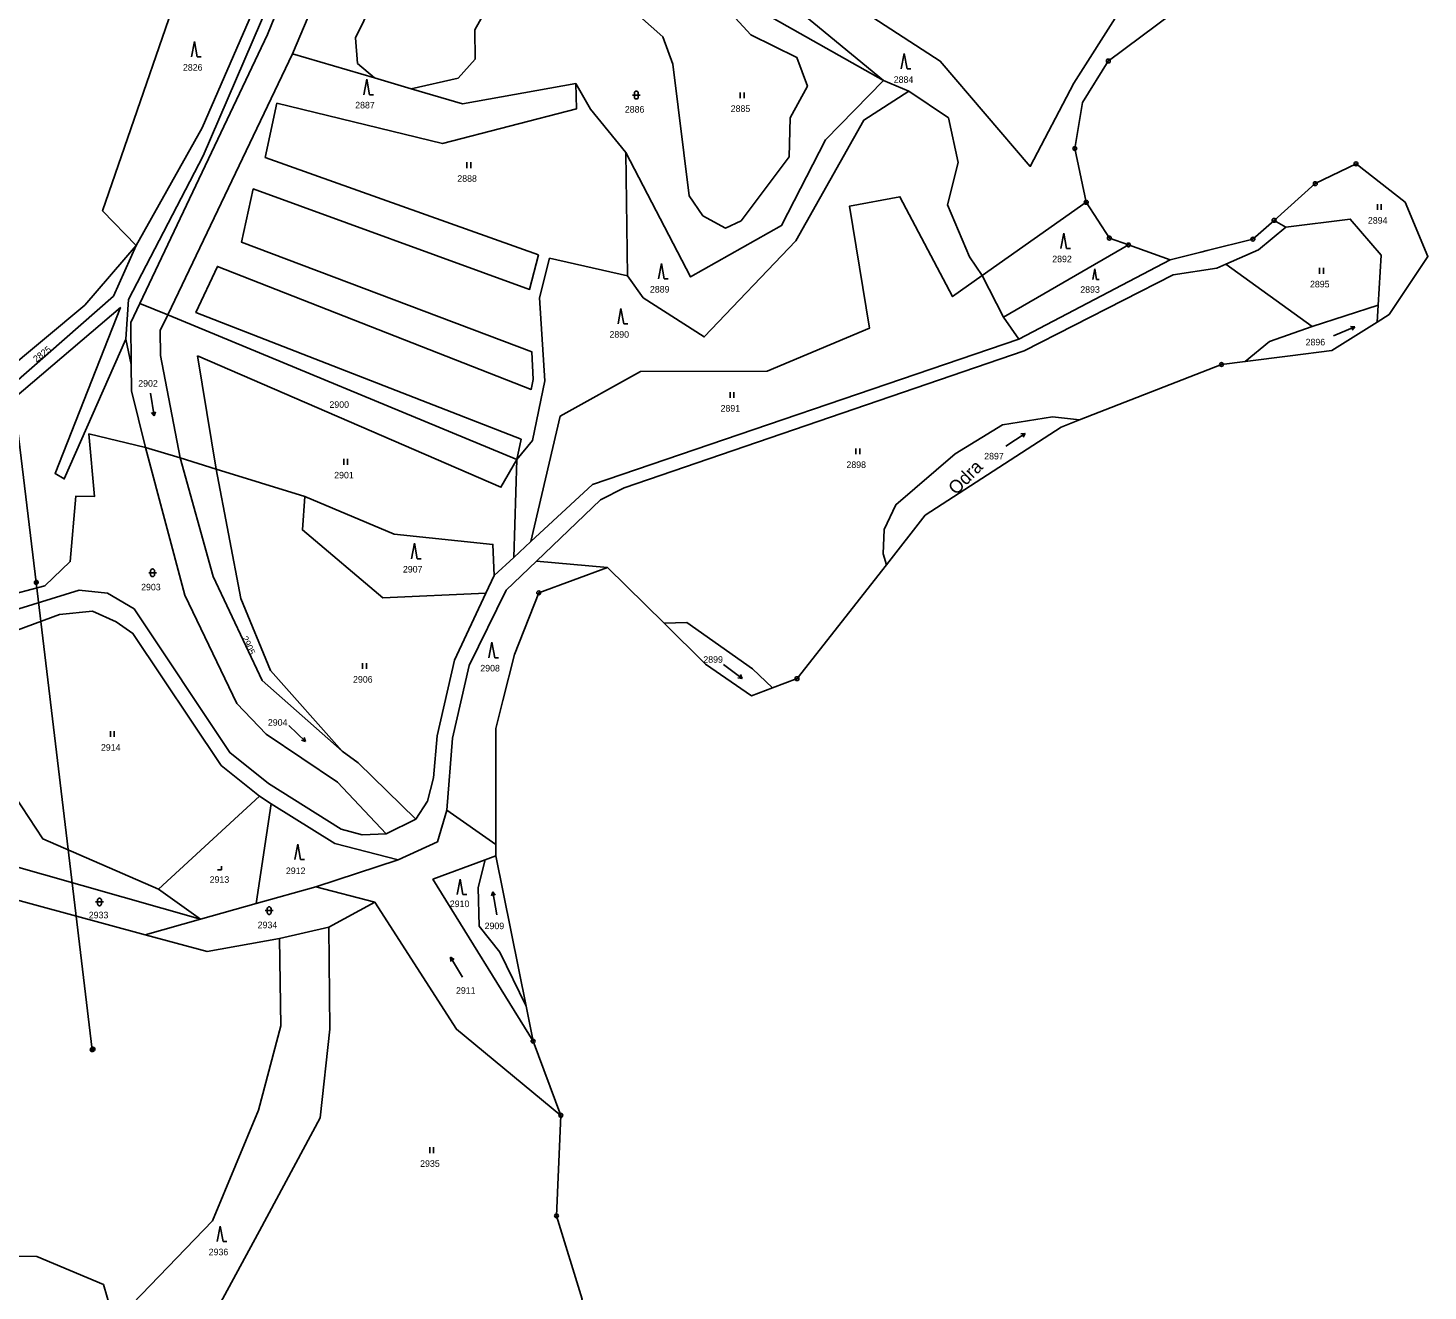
# Model space of a CAD drawing. Extents: x -504988 to -494607, y -1123820 to -1114018.
# Drawn here: x -496650.7 to -496288.6, y -1121578.3 to -1121251.8 of the extents above; entities that cross this region are included whole.
import ezdxf

# ---------------------------------------------------------------- set-up
doc = ezdxf.new("R2010")
doc.units = 0
for name, color, linetype in [('Hranice parcel', 7, 'Continuous'), ('Parcelní čísla', 7, 'Continuous'), ('Pop  PČ popisy', 7, 'Continuous'), ('Poz předměty', 7, 'Continuous'), ('Značky bodu BP', 7, 'Continuous'), ('Značky kultur', 7, 'Continuous')]:
    doc.layers.add(name, color=color, linetype=linetype)

msp = doc.modelspace()

# ---------------------------------------------------------------- linework, layer by layer
at = {"layer": 'Hranice parcel'}
for p, q in [((-496470.68, -1121231.3), (-496429.48, -1121265.34)), ((-496429.48, -1121265.34), (-496476.36, -1121238.83)), ((-496582.31, -1121258.44), (-496614.58, -1121325.9)), ((-496561.1, -1121264.68), (-496582.31, -1121258.44)), ((-496551.6, -1121267.48), (-496561.1, -1121264.68)), ((-496429.48, -1121265.34), (-496422.9, -1121268.07)), ((-496422.9, -1121268.07), (-496412.65, -1121274.96)), ((-496495.64, -1121315.83), (-496496.12, -1121283.91)), ((-496403.9, -1121315.79), (-496377.01, -1121296.83)), ((-496325.37, -1121303.26), (-496332.46, -1121309.1)), ((-496328.42, -1121301.49), (-496325.37, -1121303.26)), ((-496398.42, -1121326.56), (-496366.07, -1121307.85)), ((-496355.33, -1121311.69), (-496366.07, -1121307.85)), ((-496332.46, -1121309.1), (-496340.89, -1121312.79)), ((-496515.81, -1121311.23), (-496495.64, -1121315.83)), ((-496394.48, -1121332.18), (-496355.33, -1121311.69)), ((-496340.89, -1121312.79), (-496318.62, -1121328.96)), ((-496398.42, -1121326.56), (-496403.9, -1121315.79)), ((-496621.74, -1121322.97), (-496614.58, -1121325.9)), ((-496318.62, -1121328.96), (-496301.51, -1121323.39)), ((-496301.51, -1121323.39), (-496301.79, -1121327.79)), ((-496524.26, -1121363.37), (-496614.58, -1121325.9)), ((-496394.48, -1121332.18), (-496398.42, -1121326.56)), ((-496301.79, -1121327.79), (-496298.64, -1121325.8)), ((-496624.02, -1121338.8), (-496625.44, -1121332.21)), ((-496504.73, -1121369.78), (-496394.48, -1121332.18)), ((-496602.07, -1121365.82), (-496606.86, -1121336.5)), ((-496383.53, -1121354.95), (-496378.78, -1121353.1)), ((-496620.34, -1121360.24), (-496611.32, -1121362.94)), ((-496524.26, -1121363.37), (-496523.18, -1121358.1)), ((-496524.26, -1121363.37), (-496520.22, -1121358.42)), ((-496611.32, -1121362.94), (-496602.07, -1121365.82)), ((-496525.08, -1121388.67), (-496524.26, -1121363.37)), ((-496602.07, -1121365.82), (-496579.07, -1121372.92)), ((-496595.65, -1121399.25), (-496602.07, -1121365.82)), ((-496520.67, -1121384.57), (-496504.73, -1121369.78)), ((-496525.08, -1121388.67), (-496520.67, -1121384.57)), ((-496530.13, -1121393.36), (-496525.08, -1121388.67)), ((-496519.17, -1121389.66), (-496500.84, -1121391.27)), ((-496530.13, -1121393.36), (-496532.29, -1121397.87)), ((-496500.84, -1121391.27), (-496486.21, -1121405.66)), ((-496569.41, -1121438.72), (-496590.16, -1121420.45)), ((-496565.28, -1121441.81), (-496569.41, -1121438.72)), ((-496550.42, -1121456.31), (-496565.28, -1121441.81)), ((-496616.96, -1121474.47), (-496590.86, -1121450.37)), ((-496590.86, -1121450.37), (-496587.81, -1121452.35)), ((-496587.81, -1121452.35), (-496591.67, -1121478.13)), ((-496542.35, -1121453.98), (-496529.73, -1121462.92)), ((-496550.42, -1121456.31), (-496558.08, -1121460.12)), ((-496529.73, -1121465.85), (-496532.47, -1121466.87)), ((-496529.73, -1121465.85), (-496529.73, -1121462.92)), ((-496521.89, -1121504.73), (-496529.73, -1121465.85)), ((-496554.97, -1121466.82), (-496576.27, -1121473.8)), ((-496620.4, -1121486.22), (-496662.4, -1121474.88)), ((-496606.05, -1121482.18), (-496616.96, -1121474.47)), ((-496591.67, -1121478.13), (-496576.27, -1121473.8)), ((-496576.27, -1121473.8), (-496560.96, -1121477.77)), ((-496591.67, -1121478.13), (-496606.05, -1121482.18)), ((-496572.91, -1121484.29), (-496560.96, -1121477.77)), ((-496620.4, -1121486.22), (-496606.05, -1121482.18)), ((-496585.65, -1121487.21), (-496572.91, -1121484.29)), ((-496604.4, -1121490.57), (-496620.4, -1121486.22)), ((-496585.65, -1121487.21), (-496604.4, -1121490.57)), ((-496520.07, -1121513.73), (-496521.89, -1121504.73)), ((-496512.9, -1121532.93), (-496520.07, -1121513.73)), ((-496590.79, -1121562.78), (-496604.12, -1121587.34))]:
    msp.add_line(p, q, dxfattribs=at)
for points in [[(-496528.08, -1121099.62), (-496543.62, -1121159.94), (-496554.91, -1121193.59), (-496582.31, -1121258.44)], [(-496625.44, -1121332.21), (-496624.69, -1121321.94), (-496605.39, -1121284.77), (-496573.58, -1121210.9), (-496558.7, -1121173.54), (-496551.05, -1121143.84), (-496538.11, -1121103.1)], [(-496538.11, -1121103.1), (-496539.96, -1121118.77), (-496556.52, -1121174.22), (-496588.8, -1121253.45), (-496621.74, -1121322.97)], [(-496475.72, -1121131.99), (-496375.19, -1121228.76), (-496368.33, -1121247.28), (-496380.21, -1121266), (-496391.51, -1121287.55), (-496414.78, -1121260.32), (-496466.99, -1121226.41)], [(-496561.1, -1121264.68), (-496565.51, -1121260.92), (-496565.99, -1121254.26), (-496538.21, -1121197.62), (-496535.05, -1121173.52), (-496531.79, -1121155.63), (-496528.33, -1121152.95), (-496525.09, -1121154.94)], [(-496606.21, -1121225.85), (-496631.4, -1121299.05), (-496622.71, -1121308.03)], [(-496514.87, -1121236.67), (-496517.64, -1121243.89), (-496532.34, -1121247.33), (-496535.12, -1121252.25), (-496535.06, -1121259.82), (-496539.41, -1121264.69), (-496551.6, -1121267.48)], [(-496588.6, -1121238.29), (-496605.69, -1121277.61), (-496622.71, -1121308.03)], [(-496477.36, -1121240.16), (-496474.75, -1121241.45), (-496463.73, -1121253.49), (-496451.83, -1121259.41), (-496449.13, -1121266.76), (-496453.58, -1121275.01), (-496453.87, -1121285.05), (-496466.27, -1121301.6), (-496470.32, -1121303.48), (-496476.18, -1121300.32), (-496479.7, -1121295.16), (-496483.91, -1121261.07), (-496486.53, -1121254.02), (-496499.38, -1121242.59)], [(-496377.01, -1121296.83), (-496379.97, -1121282.91), (-496377.95, -1121271.02), (-496371.3, -1121260.29), (-496350.41, -1121244.73)], [(-496518.7, -1121310.41), (-496589.33, -1121285.21), (-496586.34, -1121271.23), (-496543.49, -1121281.61), (-496508.86, -1121272.69), (-496509.04, -1121266.08)], [(-496551.6, -1121267.48), (-496538.34, -1121271.38), (-496509.04, -1121266.08)], [(-496509.04, -1121266.08), (-496505.23, -1121272.77), (-496496.12, -1121283.91)], [(-496496.12, -1121283.91), (-496479.32, -1121316.11), (-496455.8, -1121302.85), (-496444.46, -1121280.63), (-496429.48, -1121265.34)], [(-496495.64, -1121315.83), (-496491.58, -1121321.57), (-496475.8, -1121331.64), (-496452.12, -1121306.76), (-496434.53, -1121275.57), (-496422.9, -1121268.07)], [(-496412.65, -1121274.96), (-496410.16, -1121286.57), (-496412.87, -1121297.47)], [(-496307.24, -1121286.88), (-496317.77, -1121292), (-496328.42, -1121301.49)], [(-496298.64, -1121325.8), (-496288.62, -1121310.83), (-496294.56, -1121296.8), (-496307.24, -1121286.88)], [(-496523.18, -1121358.1), (-496607.26, -1121325.32), (-496601.73, -1121313.42), (-496520.55, -1121345.23), (-496520.02, -1121342.67), (-496520.39, -1121335.52), (-496595.47, -1121307.14), (-496592.46, -1121293.36), (-496520.96, -1121319.37), (-496518.7, -1121310.41)], [(-496520.67, -1121384.57), (-496513.05, -1121352.11), (-496492.32, -1121340.62), (-496459.56, -1121340.51), (-496433.09, -1121329.39), (-496438.26, -1121297.83), (-496425.2, -1121295.38), (-496411.56, -1121321.19), (-496403.9, -1121315.79)], [(-496412.87, -1121297.47), (-496407.24, -1121310.9), (-496403.9, -1121315.79)], [(-496366.07, -1121307.85), (-496371.03, -1121306.08), (-496377.01, -1121296.83)], [(-496328.42, -1121301.49), (-496333.9, -1121306.37), (-496345.7, -1121309.3), (-496347.4, -1121309.72), (-496355.33, -1121311.69)], [(-496325.37, -1121303.26), (-496308.71, -1121301.15), (-496300.69, -1121310.53), (-496301.51, -1121323.39)], [(-496622.71, -1121308.03), (-496636.01, -1121323.43), (-496668.45, -1121350.39), (-496671.83, -1121352.39)], [(-496622.71, -1121308.03), (-496628.61, -1121321.12), (-496667.38, -1121355.04)], [(-496520.22, -1121358.42), (-496517, -1121343.01), (-496518.43, -1121321.57), (-496515.81, -1121311.23)], [(-496519.17, -1121389.66), (-496502.65, -1121373.74), (-496496.53, -1121370.66), (-496393.03, -1121335.2), (-496354.54, -1121315.56), (-496343.25, -1121313.82), (-496340.89, -1121312.79)], [(-496667.38, -1121355.04), (-496664.77, -1121356.36), (-496626.79, -1121324.03), (-496643.72, -1121366.96), (-496641.34, -1121368.36), (-496625.44, -1121332.21)], [(-496621.74, -1121322.97), (-496624.1, -1121327.94), (-496624.02, -1121338.8)], [(-496614.58, -1121325.9), (-496616.52, -1121329.94), (-496616.41, -1121336.44), (-496611.32, -1121362.94)], [(-496335.88, -1121338), (-496324.29, -1121336.54), (-496313.45, -1121335.17), (-496301.79, -1121327.79)], [(-496318.62, -1121328.96), (-496329.64, -1121332.86), (-496335.88, -1121338)], [(-496624.02, -1121338.8), (-496623.97, -1121345.57), (-496620.34, -1121360.24)], [(-496606.86, -1121336.5), (-496528.4, -1121370.53), (-496524.26, -1121363.37)], [(-496378.78, -1121353.1), (-496342.03, -1121338.78), (-496335.88, -1121338)], [(-496378.78, -1121353.1), (-496385.72, -1121352.32), (-496398.7, -1121354.35), (-496410.9, -1121361.85), (-496426.29, -1121375.04), (-496429.23, -1121381.46), (-496429.49, -1121387.76), (-496428.7, -1121390.55)], [(-496620.34, -1121360.24), (-496634.95, -1121356.72), (-496633.53, -1121372.93), (-496638.31, -1121372.79), (-496639.77, -1121389.71), (-496646.34, -1121396), (-496668.66, -1121401.9)], [(-496428.7, -1121390.55), (-496418.63, -1121377.71), (-496383.53, -1121354.95)], [(-496558.08, -1121460.12), (-496570.66, -1121446.78), (-496589.12, -1121434.38), (-496596.69, -1121426.45), (-496610.16, -1121398.44), (-496620.34, -1121360.24)], [(-496590.16, -1121420.45), (-496602.79, -1121393.6), (-496611.32, -1121362.94)], [(-496532.29, -1121397.87), (-496558.93, -1121399.13), (-496579.74, -1121381.55), (-496579.07, -1121372.92)], [(-496579.07, -1121372.92), (-496556.04, -1121382.68), (-496530.47, -1121385.29), (-496530.13, -1121393.36)], [(-496542.35, -1121453.98), (-496540.95, -1121435.35), (-496536.64, -1121416.56), (-496527.06, -1121397.15), (-496519.17, -1121389.66)], [(-496524.89, -1121413.73), (-496518.62, -1121397.8), (-496500.84, -1121391.27)], [(-496458.13, -1121422.4), (-496451.81, -1121420), (-496428.7, -1121390.55)], [(-496558.08, -1121460.12), (-496564.28, -1121460.43), (-496569.68, -1121458.96), (-496588.54, -1121447.1), (-496598.53, -1121439.12), (-496623.23, -1121401.96), (-496630.14, -1121397.89), (-496637.5, -1121397.15), (-496656.69, -1121403.1), (-496668.66, -1121401.9)], [(-496569.41, -1121438.72), (-496588.01, -1121417.93), (-496595.65, -1121399.25)], [(-496532.29, -1121397.87), (-496540.44, -1121415.25), (-496544.92, -1121434.75), (-496545.83, -1121445.67), (-496547.4, -1121451.7), (-496550.42, -1121456.31)], [(-496666.89, -1121406.29), (-496655.87, -1121408.36), (-496642.6, -1121403.41), (-496634.03, -1121402.52), (-496627.92, -1121405.3), (-496623.56, -1121408.29), (-496600.71, -1121442.49), (-496590.86, -1121450.37)], [(-496666.89, -1121406.29), (-496655.19, -1121437.57), (-496654.1, -1121450.38), (-496646.83, -1121461.45), (-496616.96, -1121474.47)], [(-496486.21, -1121405.66), (-496480.28, -1121405.44), (-496463.33, -1121417.49), (-496458.13, -1121422.4)], [(-496486.21, -1121405.66), (-496475.47, -1121416.23), (-496463.61, -1121424.48), (-496458.13, -1121422.4)], [(-496529.73, -1121462.92), (-496529.72, -1121442.66), (-496529.72, -1121432.92), (-496527.9, -1121425.68), (-496524.89, -1121413.73)], [(-496587.81, -1121452.35), (-496571.36, -1121462.63), (-496554.97, -1121466.82)], [(-496554.97, -1121466.82), (-496544.8, -1121462.19), (-496542.35, -1121453.98)], [(-496662.87, -1121463.73), (-496656.68, -1121467.79), (-496606.05, -1121482.18)], [(-496532.47, -1121466.87), (-496545.96, -1121471.86), (-496520.07, -1121513.73)], [(-496532.47, -1121466.87), (-496534.24, -1121474.02), (-496534.02, -1121483.97), (-496528.7, -1121490.71), (-496521.89, -1121504.73)], [(-496560.96, -1121477.77), (-496539.85, -1121510.68), (-496512.9, -1121532.93)], [(-496572.91, -1121484.29), (-496572.66, -1121510.67), (-496575.11, -1121533.56), (-496590.79, -1121562.78)], [(-496591.11, -1121531.58), (-496585.32, -1121509.8), (-496585.65, -1121487.21)], [(-496628.32, -1121586.51), (-496602.98, -1121560.16), (-496591.11, -1121531.58)], [(-496514.28, -1121602.59), (-496507.37, -1121580.43), (-496514.02, -1121558.9), (-496512.9, -1121532.93)], [(-496628.32, -1121586.51), (-496631.2, -1121576.69), (-496648.43, -1121569.4), (-496668.19, -1121569.15), (-496679.47, -1121580.69), (-496681.86, -1121588.4), (-496679.69, -1121596.75)]]:
    msp.add_lwpolyline(points, dxfattribs=at)
at = {"layer": 'Poz předměty'}
for p, q in [((-496662.04, -1121284.27), (-496648.56, -1121395.11)), ((-496648.56, -1121395.11), (-496634.09, -1121515.95))]:
    msp.add_line(p, q, dxfattribs=at)
for centre, radius in [((-496648.56, -1121395.11), 0.5), ((-496648.56, -1121395.11), 0.4), ((-496648.56, -1121395.11), 0.3), ((-496648.56, -1121395.11), 0.2), ((-496648.56, -1121395.11), 0.1), ((-496634.09, -1121515.95), 0.5), ((-496634.09, -1121515.95), 0.4), ((-496633.89, -1121515.82), 0.5), ((-496634.09, -1121515.95), 0.3), ((-496633.89, -1121515.82), 0.4), ((-496634.09, -1121515.95), 0.2), ((-496633.89, -1121515.82), 0.3), ((-496634.09, -1121515.95), 0.1), ((-496633.89, -1121515.82), 0.2), ((-496633.89, -1121515.82), 0.1)]:
    msp.add_circle(centre, radius, dxfattribs=at)
at = {"layer": 'Značky bodu BP'}
for centre, radius in [((-496371.3, -1121260.29), 0.5), ((-496371.3, -1121260.29), 0.0303), ((-496379.97, -1121282.91), 0.5), ((-496379.97, -1121282.91), 0.0303), ((-496307.24, -1121286.88), 0.5), ((-496307.24, -1121286.88), 0.0303), ((-496317.77, -1121292), 0.5), ((-496317.77, -1121292), 0.0303), ((-496377.01, -1121296.83), 0.5), ((-496377.01, -1121296.83), 0.0303), ((-496328.42, -1121301.49), 0.5), ((-496328.42, -1121301.49), 0.0303), ((-496371.03, -1121306.08), 0.5), ((-496371.03, -1121306.08), 0.0303), ((-496333.9, -1121306.37), 0.5), ((-496333.9, -1121306.37), 0.0303), ((-496366.07, -1121307.85), 0.5), ((-496366.07, -1121307.85), 0.0303), ((-496342.03, -1121338.78), 0.5), ((-496342.03, -1121338.78), 0.0303), ((-496518.62, -1121397.8), 0.5), ((-496518.62, -1121397.8), 0.0303), ((-496451.81, -1121420), 0.5), ((-496451.81, -1121420), 0.0303), ((-496520.07, -1121513.73), 0.5), ((-496520.07, -1121513.73), 0.0303), ((-496512.9, -1121532.93), 0.5), ((-496512.9, -1121532.93), 0.0303), ((-496514.02, -1121558.9), 0.5), ((-496514.02, -1121558.9), 0.0303)]:
    msp.add_circle(centre, radius, dxfattribs=at)
at = {"layer": 'Značky kultur'}
for p, q in [((-496607.66, -1121255.24), (-496608.41, -1121259.24)), ((-496606.91, -1121259.24), (-496607.66, -1121255.24)), ((-496606.91, -1121259.24), (-496605.91, -1121259.24)), ((-496424.09, -1121258.33), (-496424.84, -1121262.33)), ((-496423.34, -1121262.33), (-496424.09, -1121258.33)), ((-496423.34, -1121262.33), (-496422.34, -1121262.33)), ((-496563.11, -1121265), (-496563.86, -1121269)), ((-496562.36, -1121269), (-496563.11, -1121265)), ((-496562.36, -1121269), (-496561.36, -1121269)), ((-496494.37, -1121269.09), (-496492.37, -1121269.09)), ((-496493.87, -1121268.59), (-496493.87, -1121269.59)), ((-496492.87, -1121269.59), (-496492.87, -1121268.59)), ((-496466.5, -1121269.91), (-496466.5, -1121268.41)), ((-496465.5, -1121269.91), (-496465.5, -1121268.41)), ((-496537.21, -1121287.98), (-496537.21, -1121286.48)), ((-496536.21, -1121287.98), (-496536.21, -1121286.48)), ((-496301.7, -1121298.81), (-496301.7, -1121297.31)), ((-496300.7, -1121298.81), (-496300.7, -1121297.31)), ((-496382.83, -1121304.77), (-496383.58, -1121308.77)), ((-496382.08, -1121308.77), (-496382.83, -1121304.77)), ((-496382.08, -1121308.77), (-496381.08, -1121308.77)), ((-496486.88, -1121312.62), (-496487.63, -1121316.62)), ((-496486.13, -1121316.62), (-496486.88, -1121312.62)), ((-496374.82, -1121314.07), (-496375.32, -1121316.75)), ((-496374.32, -1121316.75), (-496374.82, -1121314.07)), ((-496316.68, -1121315.28), (-496316.68, -1121313.78)), ((-496315.68, -1121315.28), (-496315.68, -1121313.78)), ((-496486.13, -1121316.62), (-496485.13, -1121316.62)), ((-496374.32, -1121316.75), (-496373.65, -1121316.75)), ((-496497.35, -1121324.29), (-496498.1, -1121328.29)), ((-496496.6, -1121328.29), (-496497.35, -1121324.29)), ((-496496.6, -1121328.29), (-496495.6, -1121328.29)), ((-496313.06, -1121331.35), (-496307.54, -1121329.01)), ((-496307.54, -1121329.01), (-496308.64, -1121328.93)), ((-496307.54, -1121329.01), (-496308.24, -1121329.85)), ((-496619.02, -1121346.15), (-496618.08, -1121352.07)), ((-496469.12, -1121347.39), (-496469.12, -1121345.89)), ((-496468.12, -1121347.39), (-496468.12, -1121345.89)), ((-496618.08, -1121352.07), (-496618.73, -1121351.19)), ((-496618.08, -1121352.07), (-496617.73, -1121351.03)), ((-496397.83, -1121359.85), (-496392.79, -1121356.58)), ((-496392.79, -1121356.58), (-496393.89, -1121356.7)), ((-496392.79, -1121356.58), (-496393.34, -1121357.54)), ((-496436.57, -1121361.98), (-496436.57, -1121360.48)), ((-496435.57, -1121361.98), (-496435.57, -1121360.48)), ((-496569.05, -1121364.68), (-496569.05, -1121363.18)), ((-496568.05, -1121364.68), (-496568.05, -1121363.18)), ((-496550.77, -1121385.01), (-496551.52, -1121389.01)), ((-496550.02, -1121389.01), (-496550.77, -1121385.01)), ((-496550.02, -1121389.01), (-496549.02, -1121389.01)), ((-496619.48, -1121392.63), (-496617.48, -1121392.63)), ((-496618.98, -1121392.13), (-496618.98, -1121393.13)), ((-496617.98, -1121393.13), (-496617.98, -1121392.13)), ((-496530.75, -1121410.59), (-496531.5, -1121414.59)), ((-496530, -1121414.59), (-496530.75, -1121410.59)), ((-496530, -1121414.59), (-496529, -1121414.59)), ((-496564.18, -1121417.49), (-496564.18, -1121415.99)), ((-496563.18, -1121417.49), (-496563.18, -1121415.99)), ((-496470.79, -1121416.34), (-496466, -1121419.95)), ((-496466, -1121419.95), (-496466.47, -1121418.96)), ((-496466, -1121419.95), (-496467.08, -1121419.77)), ((-496629.38, -1121435.09), (-496629.38, -1121433.59)), ((-496628.38, -1121435.09), (-496628.38, -1121433.59)), ((-496583.21, -1121432.1), (-496578.9, -1121436.27)), ((-496578.9, -1121436.27), (-496579.95, -1121435.95)), ((-496578.9, -1121436.27), (-496579.25, -1121435.23)), ((-496580.95, -1121462.8), (-496581.7, -1121466.8)), ((-496580.2, -1121466.8), (-496580.95, -1121462.8)), ((-496601.7, -1121469.48), (-496600.7, -1121469.48)), ((-496600.7, -1121469.48), (-496600.7, -1121468.48)), ((-496580.2, -1121466.8), (-496579.2, -1121466.8)), ((-496538.97, -1121471.84), (-496539.72, -1121475.84)), ((-496538.22, -1121475.84), (-496538.97, -1121471.84)), ((-496538.22, -1121475.84), (-496537.22, -1121475.84)), ((-496530.52, -1121475.15), (-496530.84, -1121476.2)), ((-496529.47, -1121481.06), (-496530.52, -1121475.15)), ((-496530.52, -1121475.15), (-496529.85, -1121476.02)), ((-496633.21, -1121477.75), (-496631.21, -1121477.75)), ((-496632.71, -1121477.25), (-496632.71, -1121478.25)), ((-496631.71, -1121478.25), (-496631.71, -1121477.25)), ((-496589.33, -1121479.99), (-496587.33, -1121479.99)), ((-496588.83, -1121479.49), (-496588.83, -1121480.49)), ((-496587.83, -1121480.49), (-496587.83, -1121479.49)), ((-496538.36, -1121497.19), (-496541.45, -1121492.05)), ((-496541.45, -1121492.05), (-496541.37, -1121493.15)), ((-496541.45, -1121492.05), (-496540.51, -1121492.63)), ((-496546.82, -1121542.69), (-496546.82, -1121541.19)), ((-496545.82, -1121542.69), (-496545.82, -1121541.19)), ((-496601, -1121561.56), (-496601.75, -1121565.56)), ((-496600.25, -1121565.56), (-496601, -1121561.56)), ((-496600.25, -1121565.56), (-496599.25, -1121565.56))]:
    msp.add_line(p, q, dxfattribs=at)
for centre, start, end in [((-496493.37, -1121268.59), 0, 180), ((-496493.37, -1121269.59), 180, 359.9879), ((-496618.48, -1121392.13), 0, 180), ((-496618.48, -1121393.13), 180, 359.9879), ((-496632.21, -1121477.25), 0, 180), ((-496632.21, -1121478.25), 180, 359.9879), ((-496588.33, -1121479.49), 0, 180), ((-496588.33, -1121480.49), 180, 359.9879)]:
    msp.add_arc(centre, 0.5, start, end, dxfattribs=at)

# ---------------------------------------------------------------- texts
at = {"layer": 'Parcelní čísla'}
for s, p in [('2826', (-496610.63, -1121262.79)), ('2884', (-496426.8, -1121265.95)), ('2887', (-496566.08, -1121272.55)), ('2886', (-496496.34, -1121273.64)), ('2885', (-496468.96, -1121273.46)), ('2888', (-496539.67, -1121291.53)), ('2894', (-496304.16, -1121302.36)), ('2892', (-496385.8, -1121312.32)), ('2895', (-496319.14, -1121318.83)), ('2889', (-496489.85, -1121320.17)), ('2893', (-496378.55, -1121320.23)), ('2890', (-496500.32, -1121331.84)), ('2896', (-496320.27, -1121333.83)), ('2902', (-496622.19, -1121344.5)), ('2900', (-496572.74, -1121349.98)), ('2891', (-496471.58, -1121350.94)), ('2898', (-496439.03, -1121365.53)), ('2897', (-496403.4, -1121363.32)), ('2901', (-496571.51, -1121368.23)), ('2907', (-496553.74, -1121392.56)), ('2903', (-496621.45, -1121397.18)), ('2899', (-496476.04, -1121415.9)), ('2908', (-496533.72, -1121418.14)), ('2906', (-496566.64, -1121421.04)), ('2904', (-496588.66, -1121432.18)), ('2914', (-496631.84, -1121438.64)), ('2912', (-496584, -1121470.54)), ('2913', (-496603.71, -1121472.79)), ('2933', (-496634.98, -1121481.98)), ('2910', (-496541.61, -1121479.08)), ('2934', (-496591.3, -1121484.54)), ('2909', (-496532.61, -1121484.78)), ('2911', (-496540.01, -1121501.48)), ('2935', (-496549.28, -1121546.24)), ('2936', (-496603.97, -1121569.11))]:
    msp.add_text(s, height=1.7, dxfattribs=at).set_placement(p)
for s, rotation, p in [('2825', 38, (-496648.54, -1121338.28)), ('2905', 295, (-496595.52, -1121409.47))]:
    msp.add_text(s, height=1.7, rotation=rotation, dxfattribs=at).set_placement(p)
at = {"layer": 'Pop  PČ popisy'}
msp.add_text('Odra', height=3.4, rotation=45, dxfattribs=at).set_placement((-496410.66, -1121372.69))

doc.saveas('drawing.dxf')
